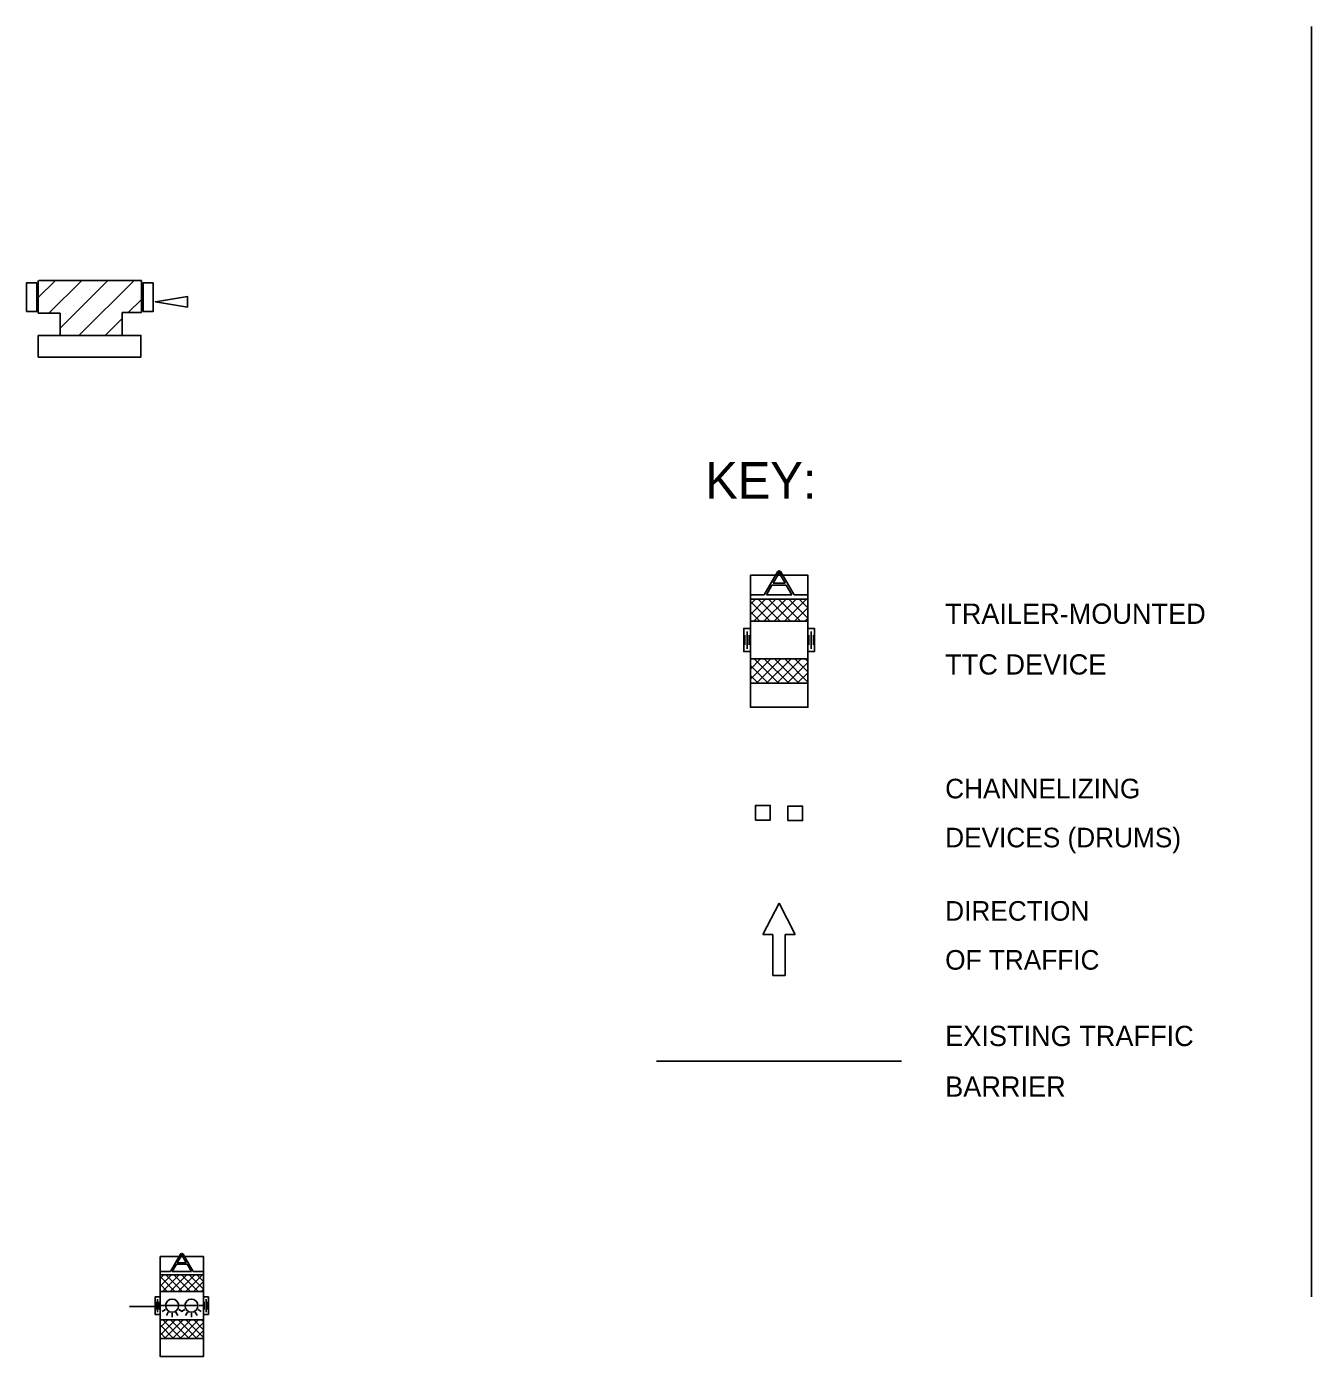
# Model space of a CAD drawing. Extents: x 9 to 25.8, y 6 to 22.7.
# Drawn here: x 10.436 to 14.369, y 11.118 to 15.19 of the extents above; entities that cross this region are included whole.
import ezdxf

# ---------------------------------------------------------------- set-up
doc = ezdxf.new("R2010")
doc.units = 0
for name, color, linetype in [('C-SIGN-FACE_N', 7, 'Continuous'), ('DETL-DIMS', 7, 'Continuous'), ('DETL-LINE', 7, 'Continuous'), ('DETL-NOTE', 7, 'Continuous'), ('DETL-TITL', 7, 'Continuous'), ('SIGN-FACE_P', 7, 'Continuous'), ('SIGN-POST_VSL', 7, 'Continuous'), ('TRAF-MISC', 7, 'Continuous'), ('USER-BORD', 7, 'Continuous')]:
    doc.layers.add(name, color=color, linetype=linetype)

# ---------------------------------------------------------------- blocks, each defined once
blk = doc.blocks.new('DIR2')
at = {"layer": 'USER-BORD'}
for p, q in [((0, 0.0001), (-0.0034, -0.0048)), ((0, 0.0001), (0.0034, -0.0048)), ((-0.0034, -0.0048), (-0.0013, -0.0048)), ((-0.0013, -0.0113), (-0.0013, -0.0048)), ((0.0034, -0.0048), (0.0013, -0.0048)), ((0.0013, -0.0113), (0.0013, -0.0048)), ((-0.0001, -0.0113), (-0.0013, -0.0113)), ((-0.0001, -0.0113), (0.0001, -0.0113)), ((0.0001, -0.0113), (0.0013, -0.0113))]:
    blk.add_line(p, q, dxfattribs=at)

msp = doc.modelspace()

# ---------------------------------------------------------------- linework, layer by layer
at = {"layer": 'C-SIGN-FACE_N'}
for p, q in [((10.8578, 11.2735), (10.8461, 11.2735)), ((10.8609, 11.2618), (10.8508, 11.2559)), ((10.8611, 11.2735), (10.9014, 11.2735)), ((10.8695, 11.2532), (10.8637, 11.2431)), ((10.8813, 11.25), (10.8813, 11.2383)), ((10.893, 11.2532), (10.8989, 11.2431)), ((10.9017, 11.2618), (10.9118, 11.2559)), ((10.9166, 11.2735), (10.905, 11.2735)), ((10.9198, 11.2618), (10.9097, 11.2559)), ((10.92, 11.2735), (10.9603, 11.2735)), ((10.9284, 11.2532), (10.9226, 11.2431)), ((10.9402, 11.25), (10.9402, 11.2383)), ((10.9519, 11.2532), (10.9578, 11.2431)), ((10.9605, 11.2618), (10.9706, 11.2559)), ((10.9637, 11.2735), (10.9754, 11.2735))]:
    msp.add_line(p, q, dxfattribs=at)
for points in [[(12.6516, 13.4369), (12.8277, 13.4369), (12.8277, 13.1792), (12.6516, 13.1792)], [(10.8441, 11.3682), (10.9773, 11.3682), (10.9773, 11.1734), (10.8441, 11.1734)]]:
    msp.add_lwpolyline(points, close=True, dxfattribs=at)
for centre in [(10.8813, 11.2735), (10.9402, 11.2735)]:
    msp.add_circle(centre, 0.0201, dxfattribs=at)
for centre in [(10.8813, 11.2735), (10.9402, 11.2735)]:
    msp.add_arc(centre, 0.0201, 360, 180, dxfattribs=at)
at = {"layer": 'DETL-DIMS'}
msp.add_lwpolyline([(10.9281, 14.331), (10.9281, 14.3637), (10.8301, 14.3474)], close=True, dxfattribs=at)
at = {"layer": 'DETL-LINE'}
for p, q in [((14.3693, 15.1901), (14.3693, 11.3001)), ((10.4356, 14.3178), (10.4356, 14.4057)), ((10.4356, 14.4057), (10.4665, 14.4057)), ((10.4665, 14.4057), (10.4665, 14.3178)), ((10.4714, 14.3601), (10.5241, 14.4128)), ((10.4714, 14.3125), (10.4714, 14.4128)), ((10.4729, 14.4128), (10.787, 14.4128)), ((10.504, 14.3125), (10.6044, 14.4128)), ((10.5389, 14.2671), (10.6846, 14.4128)), ((10.5967, 14.2448), (10.7648, 14.4128)), ((10.787, 14.4128), (10.787, 14.3142)), ((10.7928, 14.4057), (10.8236, 14.4057)), ((10.7928, 14.3178), (10.7928, 14.4057)), ((10.8236, 14.4057), (10.8236, 14.3178)), ((10.7464, 14.3143), (10.787, 14.3548)), ((10.4665, 14.3178), (10.4356, 14.3178)), ((10.5389, 14.3125), (10.4714, 14.3125)), ((10.5389, 14.2443), (10.5389, 14.3125)), ((10.677, 14.2448), (10.7283, 14.2961)), ((10.7283, 14.3142), (10.7283, 14.2443)), ((10.787, 14.3142), (10.7283, 14.3142)), ((10.8236, 14.3178), (10.7928, 14.3178)), ((10.4714, 14.1779), (10.4714, 14.2443)), ((10.4714, 14.2443), (10.7855, 14.2443)), ((10.7855, 14.2443), (10.7855, 14.1779)), ((10.7855, 14.1779), (10.4714, 14.1779)), ((12.3646, 12.0219), (13.1146, 12.0219))]:
    msp.add_line(p, q, dxfattribs=at)
for points in [[(10.4665, 14.4057), (10.4357, 14.4057), (10.4357, 14.3178), (10.4665, 14.3178)], [(10.8236, 14.4057), (10.7928, 14.4057), (10.7928, 14.3178), (10.8236, 14.3178)], [(10.4714, 14.2443), (10.7855, 14.2443), (10.7855, 14.1779), (10.4714, 14.1779)], [(12.6678, 12.7604), (12.7126, 12.7604), (12.7126, 12.8052), (12.6678, 12.8052)], [(12.7667, 12.7586), (12.8115, 12.7586), (12.8115, 12.8034), (12.7667, 12.8034)]]:
    msp.add_lwpolyline(points, close=True, dxfattribs=at)
at = {"layer": 'SIGN-FACE_P'}
for p, q in [((12.6516, 13.4501), (12.6516, 13.4369)), ((12.8277, 13.4501), (12.8277, 13.4369)), ((10.8441, 11.3782), (10.8441, 11.3682)), ((10.9773, 11.3782), (10.9773, 11.3682))]:
    msp.add_line(p, q, dxfattribs=at)
at = {"layer": 'SIGN-POST_VSL'}
msp.add_line((10.8441, 11.2708), (10.7502, 11.2708), dxfattribs=at)
for points in [[(12.6516, 13.51), (12.8277, 13.51), (12.8277, 13.106), (12.6516, 13.106)], [(10.8441, 11.4235), (10.9773, 11.4235), (10.9773, 11.1181), (10.8441, 11.1181)]]:
    msp.add_lwpolyline(points, close=True, dxfattribs=at)
at = {"layer": 'TRAF-MISC'}
for p, q in [((12.694, 13.4501), (12.7345, 13.5203)), ((12.7853, 13.4501), (12.7447, 13.5203)), ((12.7008, 13.4501), (12.7178, 13.4795)), ((12.7178, 13.4795), (12.7615, 13.4795)), ((12.7212, 13.4854), (12.7367, 13.5122)), ((12.7212, 13.4854), (12.7581, 13.4854)), ((12.7581, 13.4854), (12.7426, 13.5122)), ((12.7785, 13.4501), (12.7615, 13.4795)), ((12.6516, 13.4501), (12.694, 13.4501)), ((12.7008, 13.4501), (12.7785, 13.4501)), ((12.7853, 13.4501), (12.8277, 13.4501)), ((12.6516, 13.4369), (12.6516, 13.3693)), ((12.6516, 13.3901), (12.6983, 13.4369)), ((12.6516, 13.4214), (12.667, 13.4369)), ((12.6516, 13.4296), (12.7119, 13.3693)), ((12.6516, 13.3983), (12.6806, 13.3693)), ((12.662, 13.3693), (12.7296, 13.4369)), ((12.6756, 13.4369), (12.7431, 13.3693)), ((12.6933, 13.3693), (12.7608, 13.4369)), ((12.7068, 13.4369), (12.7744, 13.3693)), ((12.7245, 13.3693), (12.7921, 13.4369)), ((12.7381, 13.4369), (12.8056, 13.3693)), ((12.7558, 13.3693), (12.8233, 13.4369)), ((12.7693, 13.4369), (12.8277, 13.3785)), ((12.787, 13.3693), (12.8277, 13.41)), ((12.8006, 13.4369), (12.8277, 13.4098)), ((12.6516, 13.3693), (12.8277, 13.3693)), ((12.8183, 13.3693), (12.8277, 13.3787)), ((12.6346, 13.3267), (12.6346, 13.2967)), ((12.6415, 13.3383), (12.6415, 13.285)), ((12.6484, 13.3267), (12.6484, 13.2967)), ((12.8308, 13.3267), (12.8308, 13.2967)), ((12.8377, 13.3383), (12.8377, 13.285)), ((12.8447, 13.3267), (12.8447, 13.2967)), ((12.8277, 13.254), (12.6516, 13.254)), ((12.6516, 13.1917), (12.7139, 13.254)), ((12.6516, 13.223), (12.6826, 13.254)), ((12.6516, 13.2341), (12.7065, 13.1792)), ((12.6629, 13.254), (12.7378, 13.1792)), ((12.6703, 13.1792), (12.7451, 13.254)), ((12.6942, 13.254), (12.769, 13.1792)), ((12.7015, 13.1792), (12.7764, 13.254)), ((12.7255, 13.254), (12.8003, 13.1792)), ((12.7328, 13.1792), (12.8076, 13.254)), ((12.7567, 13.254), (12.8277, 13.183)), ((12.764, 13.1792), (12.8277, 13.2428)), ((12.788, 13.254), (12.8277, 13.2143)), ((12.8192, 13.254), (12.8277, 13.2455)), ((12.8277, 13.1792), (12.8277, 13.254)), ((12.6516, 13.2029), (12.6753, 13.1792)), ((12.7953, 13.1792), (12.8277, 13.2116)), ((12.8265, 13.1792), (12.8277, 13.1803)), ((10.8762, 11.3782), (10.9068, 11.4312)), ((10.8968, 11.4049), (10.9085, 11.4252)), ((10.8968, 11.4049), (10.9246, 11.4049)), ((10.9246, 11.4049), (10.9129, 11.4252)), ((10.9452, 11.3782), (10.9146, 11.4312)), ((10.8441, 11.3782), (10.8762, 11.3782)), ((10.8441, 11.3682), (10.8441, 11.3171)), ((10.8441, 11.3329), (10.8795, 11.3682)), ((10.8441, 11.3565), (10.8558, 11.3682)), ((10.8441, 11.3627), (10.8897, 11.3171)), ((10.852, 11.3171), (10.9031, 11.3682)), ((10.8623, 11.3682), (10.9133, 11.3171)), ((10.8756, 11.3171), (10.9267, 11.3682)), ((10.8813, 11.3782), (10.8942, 11.4004)), ((10.8813, 11.3782), (10.9401, 11.3782)), ((10.8859, 11.3682), (10.937, 11.3171)), ((10.8942, 11.4004), (10.9272, 11.4004)), ((10.8993, 11.3171), (10.9503, 11.3682)), ((10.9095, 11.3682), (10.9606, 11.3171)), ((10.9229, 11.3171), (10.974, 11.3682)), ((10.9401, 11.3782), (10.9272, 11.4004)), ((10.9331, 11.3682), (10.9773, 11.3241)), ((10.9452, 11.3782), (10.9773, 11.3782)), ((10.9568, 11.3682), (10.9773, 11.3477)), ((10.8441, 11.3391), (10.8661, 11.3171)), ((10.9465, 11.3171), (10.9773, 11.3479)), ((10.9701, 11.3171), (10.9773, 11.3242)), ((10.8313, 11.2849), (10.8313, 11.2622)), ((10.8365, 11.2937), (10.8365, 11.2534)), ((10.8418, 11.2849), (10.8418, 11.2622)), ((10.8441, 11.3171), (10.9773, 11.3171)), ((10.9796, 11.2849), (10.9796, 11.2622)), ((10.9849, 11.2937), (10.9849, 11.2534)), ((10.9901, 11.2849), (10.9901, 11.2622)), ((10.9773, 11.23), (10.8441, 11.23)), ((10.8441, 11.1829), (10.8912, 11.23)), ((10.8441, 11.2065), (10.8676, 11.23)), ((10.8441, 11.2149), (10.8857, 11.1734)), ((10.8527, 11.23), (10.9093, 11.1734)), ((10.8583, 11.1734), (10.9148, 11.23)), ((10.8764, 11.23), (10.9329, 11.1734)), ((10.8819, 11.1734), (10.9385, 11.23)), ((10.9, 11.23), (10.9566, 11.1734)), ((10.9055, 11.1734), (10.9621, 11.23)), ((10.9236, 11.23), (10.9773, 11.1763)), ((10.9291, 11.1734), (10.9773, 11.2215)), ((10.9472, 11.23), (10.9773, 11.1999)), ((10.9709, 11.23), (10.9773, 11.2236)), ((10.9773, 11.1734), (10.9773, 11.23)), ((10.8441, 11.1913), (10.862, 11.1734)), ((10.9528, 11.1734), (10.9773, 11.1979)), ((10.9764, 11.1734), (10.9773, 11.1743))]:
    msp.add_line(p, q, dxfattribs=at)
for points in [[(12.6516, 13.4369), (12.6516, 13.1792), (12.8277, 13.1792), (12.8277, 13.4369)], [(12.6516, 13.4369), (12.8277, 13.4369), (12.8277, 13.3693), (12.6516, 13.3693)], [(12.6516, 13.3472), (12.6315, 13.3472), (12.6315, 13.2761), (12.6516, 13.2761)], [(12.8277, 13.3472), (12.8478, 13.3472), (12.8478, 13.2761), (12.8277, 13.2761)], [(12.6516, 13.254), (12.8277, 13.254), (12.8277, 13.1792), (12.6516, 13.1792)], [(10.8441, 11.3682), (10.8441, 11.1734), (10.9773, 11.1734), (10.9773, 11.3682)], [(10.8441, 11.3682), (10.9773, 11.3682), (10.9773, 11.3171), (10.8441, 11.3171)], [(10.8441, 11.3004), (10.8289, 11.3004), (10.8289, 11.2467), (10.8441, 11.2467)], [(10.9773, 11.3004), (10.9925, 11.3004), (10.9925, 11.2467), (10.9773, 11.2467)], [(10.8441, 11.23), (10.9773, 11.23), (10.9773, 11.1734), (10.8441, 11.1734)]]:
    msp.add_lwpolyline(points, close=True, dxfattribs=at)
for points in [[(12.8277, 13.3693), (12.8277, 13.4369), (12.6516, 13.4369)], [(12.6516, 13.254), (12.6516, 13.1792), (12.8277, 13.1792)], [(10.9773, 11.3171), (10.9773, 11.3682), (10.8441, 11.3682)], [(10.8441, 11.23), (10.8441, 11.1734), (10.9773, 11.1734)]]:
    msp.add_lwpolyline(points, dxfattribs=at)
for centre, radius in [((12.7396, 13.5173), 0.00589), ((12.7396, 13.5173), 0.00295), ((12.7396, 13.5173), 0.00177), ((10.9107, 11.429), 0.00446), ((10.9107, 11.429), 0.00223), ((10.9107, 11.429), 0.00134)]:
    msp.add_circle(centre, radius, dxfattribs=at)

# ---------------------------------------------------------------- block references
at = {"layer": 'DETL-LINE', "xscale": 14.56342522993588, "yscale": 19.417900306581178, "rotation": 1.0739341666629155e-12}
msp.add_blockref('DIR2', (12.7396, 12.5036), dxfattribs=at)

# ---------------------------------------------------------------- texts
at = {"layer": 'DETL-NOTE'}
for s, height, p in [('TRAILER-MOUNTED ', 0.062069, (13.2481, 13.3612)), ('TTC DEVICE', 0.06207, (13.2481, 13.206)), ('CHANNELIZING', 0.06, (13.2481, 12.8269)), ('DEVICES (DRUMS)', 0.06, (13.2481, 12.6769)), ('DIRECTION', 0.06, (13.2481, 12.4523)), ('OF TRAFFIC', 0.06, (13.2481, 12.3023)), ('EXISTING TRAFFIC', 0.062069, (13.2481, 12.0684)), ('BARRIER', 0.06207, (13.2481, 11.9133))]:
    msp.add_text(s, height=height, dxfattribs=at).set_placement(p)
at = {"layer": 'DETL-TITL'}
msp.add_text('KEY:', height=0.11172, dxfattribs=at).set_placement((12.5133, 13.7447))

doc.saveas('drawing.dxf')
